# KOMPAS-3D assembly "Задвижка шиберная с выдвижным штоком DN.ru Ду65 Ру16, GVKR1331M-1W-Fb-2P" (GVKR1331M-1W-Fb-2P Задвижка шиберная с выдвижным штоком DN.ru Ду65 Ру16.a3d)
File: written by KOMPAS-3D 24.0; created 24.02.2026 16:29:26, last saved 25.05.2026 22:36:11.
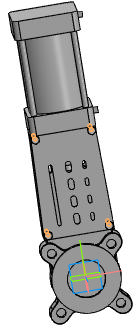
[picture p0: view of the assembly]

Document properties: Автор: R2D2; Полное имя файла: E:\Работа\Зайцев\GVKR1331M-1W-Fb-2P Задвижка шиберная с выдвижным штоком DN.ru Ду50-300 Ру16-10-6 с пневмоприводом\исходные материалы\DN65\GVKR1331M-1W-Fb-2P Задвижка шиберная с выдвижным штоком DN.ru Ду65 Ру16.a3d

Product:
- Component [detail]: Затвор дисковый DN.ru Ду Ру  | qty 1  | pos. 1  | Масса: 18.2; Раздел спецификации: Прочие изделия; Примечание: D050-23732; Автор: R2D2; source file: Задвижка шиберная РЕЗЬБОВОЙ DN.ru Ду Ру.m3d
- Component [detail]: Пневмоцилиндр  | qty 1  | pos. 2  | Масса: 16.00327; Автор: R2D2; source file: Пневмоцилиндр.m3d
- Component [standard]: Hexagon head screw ISO 4017 - М8 x 16  | qty 8  | Масса: 0.012085; Раздел спецификации: Стандартные изделия; Рассекать на разрезах: no
- Component [detail]: лист  | qty 2  | pos. 3  | Масса: 0.611304; Раздел спецификации: Прочие изделия; Примечание: D040-08800; Автор: R2D2; source file: лист.m3d
- Component [detail]: шибер  | qty 1  | pos. 4  | Масса: 0.645292; Раздел спецификации: Прочие изделия; Примечание: D040-08800; Автор: R2D2; source file: шибер.m3d
- Part/product: Задвижка шиберная с выдвижным штоком DN.ru Ду65 Ру16  | designation GVKR1331M-1W-Fb-2P
    Масса: 9.5
    Раздел спецификации: Прочие изделия
    Примечание: D040-08792

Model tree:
1. Контекстная связь:1  (with: Эскиз:1, Грань.Элемент выдавливания:15, Вершина.Элемент выдавливания:15, Ребро.Элемент выдавливания:15, Вершина.Элемент выдавливания:5, Ребро.Элемент выдавливания:5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)
2. Контекстная связь:2  (with: Эскиз:5, Ребро.Элемент выдавливания:15, Ребро.Элемент выдавливания:2, Ребро.Скругление:10, Ребро.Элемент выдавливания:1, Контекстная связь (шибер):2)
3. Контекстная связь:3  (with: Эскиз:4, Контекстная связь (Затвор дисковый DN.ru Ду Ру):3)
4. Контекстная связь:4  (with: Эскиз:5, Контекстная связь (Затвор дисковый DN.ru Ду Ру):4, Грань.Элемент выдавливания:8, Грань.Элемент выдавливания:3)  (labels: Грань.Элемент выдавливания:3.Экземпляр ( 2 ))
     Ориентация = 2; Ориентация = 2; Ориентация = 2; Ориентация = 2; Ориентация = 2

Expressions: D050-23732; D040-08800
Referenced files in E:\Работа\Зайцев\GVKR1331M-1W-Fb-2P Задвижка шиберная с выдвижным штоком DN.ru Ду50-300 Ру16-10-6 с пневмоприводом\исходные материалы\DN50\: Задвижка шиберная РЕЗЬБОВОЙ DN.ru Ду Ру.m3d, Пневмоцилиндр.m3d
Referenced files in E:\Работа\Зайцев\GVKR1331M-1W-Fb-2P Задвижка шиберная с выдвижным штоком DN.ru Ду50-300 Ру16-10-6 с пневмоприводом\исходные материалы\DN65\: Задвижка шиберная РЕЗЬБОВОЙ DN.ru Ду Ру.m3d, Пневмоцилиндр.m3d, лист.m3d, шибер.m3d
Referenced files in C:\Program Files\ASCON\KOMPAS-3D v24\Libs\PolynomLib\DATA\vault\Methods\Kompas\3D\: PLib_Bolt_1_ISO_1100.m3d
Referenced files in E:\Работа\Зайцев\GVKR1331E-1W-Fb-2P Задвижка шиберная DN.ru Ду50-300 Ру16-10-6\исходные материалы\DN50\111\: лист.m3d
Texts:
  WBV1631E-2W-Fb-R
  Затвор дисковый DN.ru Ду200 Ру16
  Hexagon head screw
  BOSimple***PART:17775d1c-e7de-f283-40f0-d40789f7f59e***SHORTLOC:A259_7B16EF33AB1642D2[13;1,25;16;8;-;Undefined]
  Программные изделия  и базы данных
  GVKR1331M-1W-Fb-2P
  Hexagon head screw ISO 4017 - М8 x 16 (1)
  hole1
  hole2
  Hexagon head screw ISO 4017 - М8 x 16 (2)
  Hexagon head screw ISO 4017 - М8 x 16 (3)
  Hexagon head screw ISO 4017 - М8 x 16 (4)
  лист (1)
  Hexagon head screw ISO 4017 - М8 x 16 (5)
  лист (2)
  Hexagon head screw ISO 4017 - М8 x 16 (6)
  Hexagon head screw ISO 4017 - М8 x 16 (7)
  Hexagon head screw ISO 4017 - М8 x 16 (8)
  Ось Y.Начало координат
  Плоскость ZY.Начало координат
  Плоскость ZX.Начало координат
  Плоскость XY.Начало координат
